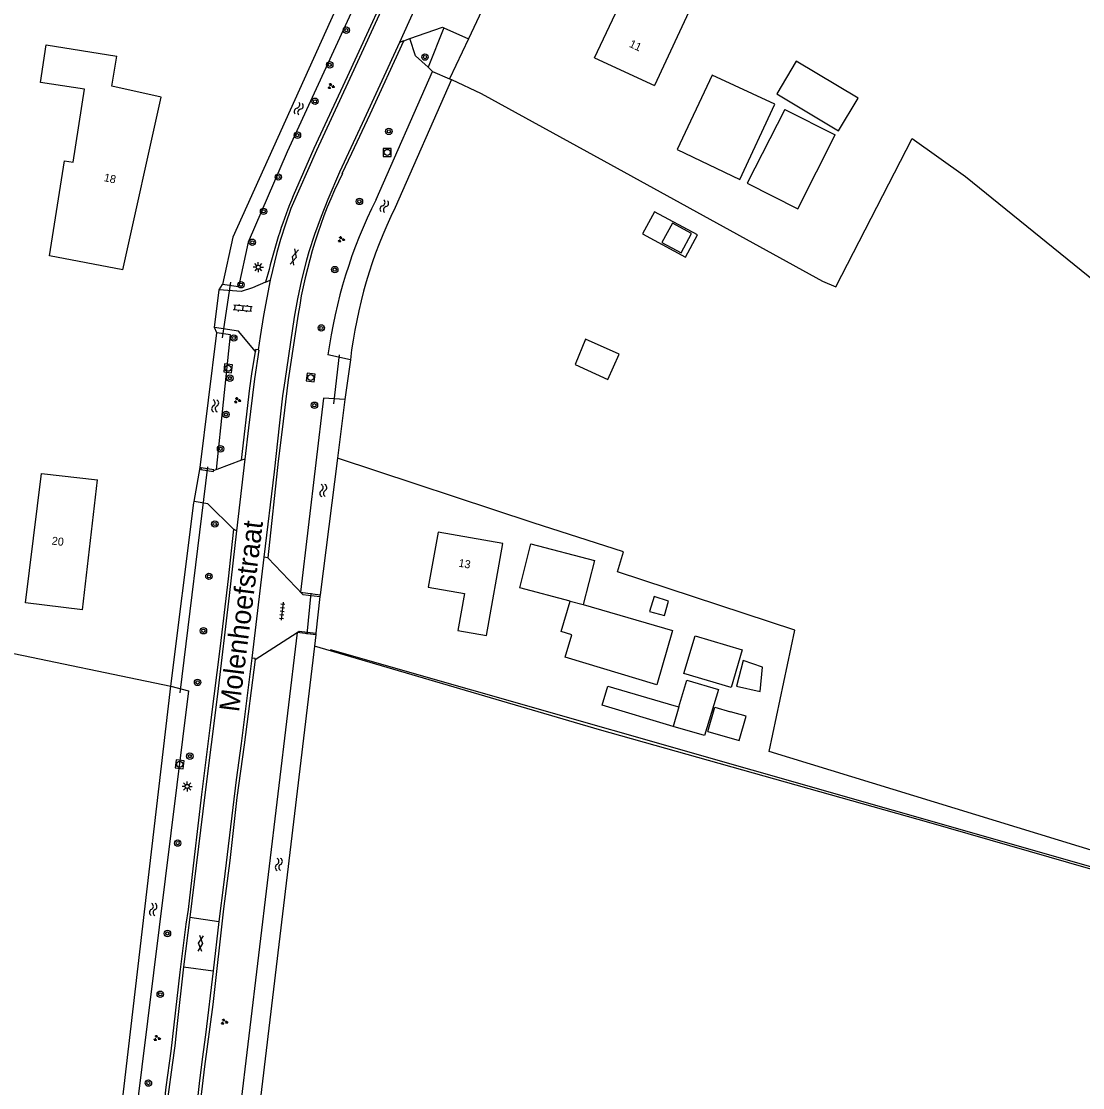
# Model space of a CAD drawing. Extents: x 136000 to 141000, y 400494 to 402006.
# Drawn here: x 137177.1 to 137309.6, y 401356.9 to 401490 of the extents above; entities that cross this region are included whole.
import ezdxf

# ---------------------------------------------------------------- set-up
doc = ezdxf.new("R2010")
doc.units = 0
for name, color, linetype in [('gg-afsc-draadraster', 7, 'Continuous'), ('gg-afsc-erfafscheiding', 7, 'Continuous'), ('gg-afsc-hekwerk', 7, 'Continuous'), ('gg-afsc-lijn draadraster', 7, 'Continuous'), ('gg-afsc-muur', 7, 'Continuous'), ('gg-anno-huisnummerreeks BGT', 7, 'Continuous'), ('gg-anno-openbare ruimte label', 7, 'Continuous'), ('gg-bbg-bijgebouw', 7, 'Continuous'), ('gg-bbg-gedigitaliseerde bebouwing', 7, 'Continuous'), ('gg-bbg-gedigitaliseerde bijgebouw', 7, 'Continuous'), ('gg-bbg-hoofdgebouw', 7, 'Continuous'), ('gg-bbg-overig bouwwerk', 7, 'Continuous'), ('gg-bbg-tussenscheiding', 7, 'Continuous'), ('gg-knt-bronhoudergrens', 7, 'Continuous'), ('gg-knt-verharding', 7, 'Continuous'), ('gg-kntw-bovenkant insteek waterloop', 7, 'Continuous'), ('gg-kntw-midden sloot', 7, 'Continuous'), ('gg-kwrk-duiker nz buis', 7, 'Continuous'), ('gt-grn-groengrens', 7, 'Continuous'), ('gt-symb-boom', 7, 'Continuous'), ('gt-symb-gesloten verharding', 7, 'Continuous'), ('gt-symb-groenvak', 7, 'Continuous'), ('gt-symb-klinker verharding', 7, 'Continuous'), ('gt-symb-lichtmast', 7, 'Continuous'), ('gt-symb-rioolschacht', 7, 'Continuous'), ('gt-symb-tegel verharding', 7, 'Continuous'), ('gt-symb-watersymbool', 7, 'Continuous')]:
    doc.layers.add(name, color=color, linetype=linetype)

# ---------------------------------------------------------------- blocks, each defined once
blk = doc.blocks.new('gt0-BOOM')
at = {"layer": 'gt-symb-boom'}
for radius in [0.4, 0.2]:
    blk.add_circle((0, 0), radius, dxfattribs=at)
blk = doc.blocks.new('gt0-WA')
at = {"layer": 'gt-symb-watersymbool'}
for centre, start, end in [((-0.32, 0.02), 28.0725, 151.9275), ((0.43, 0.42), 208.0725, 331.9275), ((-0.32, -0.43), 28.0725, 151.9275), ((0.43, -0.03), 208.0725, 331.9275)]:
    blk.add_arc(centre, 0.425, start, end, dxfattribs=at)
blk = doc.blocks.new('gt0-GRVAK')
at = {"layer": 'gt-symb-groenvak'}
for p, q in [((-0.11, 0.19), (-0.23, 0.24)), ((-0.18, 0.15), (0.09, 0.15)), ((-0.09, 0.21), (-0.16, 0.32)), ((-0.05, 0.21), (-0.05, 0.39)), ((0, 0.21), (0.06, 0.32)), ((0.02, 0.19), (0.13, 0.24)), ((0.26, -0.05), (0.2, 0.06)), ((0.3, -0.05), (0.3, 0.13)), ((0.35, -0.05), (0.41, 0.06)), ((-0.24, -0.23), (-0.36, -0.18)), ((-0.32, -0.26), (-0.05, -0.26)), ((-0.23, -0.21), (-0.29, -0.09)), ((-0.18, -0.2), (-0.18, -0.02)), ((-0.14, -0.21), (-0.07, -0.09)), ((-0.12, -0.23), (0, -0.18)), ((0.24, -0.07), (0.12, -0.02)), ((0.17, -0.11), (0.44, -0.11)), ((0.37, -0.07), (0.49, -0.02))]:
    blk.add_line(p, q, dxfattribs=at)
blk = doc.blocks.new('gt0-RS')
at = {"layer": 'gt-symb-rioolschacht'}
blk.add_lwpolyline([(-0.5, -0.5), (0.5, -0.5), (0.5, 0.5), (-0.5, 0.5)], close=True, dxfattribs=at)
blk.add_circle((0, 0), 0.375, dxfattribs=at)
blk = doc.blocks.new('gt0-LMAST')
at = {"layer": 'gt-symb-lichtmast'}
for p, q in [((-0.18, 0.17), (-0.45, 0.44)), ((-0.01, 0.25), (-0.01, 0.62)), ((0.17, 0.17), (0.44, 0.44)), ((-0.26, 0), (-0.63, 0)), ((-0.18, -0.18), (-0.45, -0.45)), ((-0.01, -0.25), (-0.01, -0.63)), ((0.44, -0.45), (0.17, -0.18)), ((0.24, 0), (0.62, 0))]:
    blk.add_line(p, q, dxfattribs=at)
blk.add_circle((-0.01, 0), 0.25, dxfattribs=at)
blk = doc.blocks.new('gt0-GESVH1')
at = {"layer": 'gt-symb-gesloten verharding'}
for p, q in [((-0.99, -0.26), (0.01, 0.24)), ((0.01, -0.26), (-0.99, 0.24)), ((0.01, 0.24), (1.01, -0.26)), ((1.01, 0.24), (0.01, -0.26))]:
    blk.add_line(p, q, dxfattribs=at)
blk = doc.blocks.new('gt0-KL1')
at = {"layer": 'gt-symb-klinker verharding'}
for p, q in [((-1.15, 0.3), (1.15, 0.3)), ((-1, -0.3), (-1, 0.3)), ((-0.5, 0.3), (-0.5, 0.45)), ((0, -0.3), (0, 0.3)), ((0.5, 0.3), (0.5, 0.45)), ((1, -0.3), (1, 0.3)), ((-1.15, -0.3), (1.15, -0.3)), ((-0.5, -0.45), (-0.5, -0.3)), ((0.5, -0.45), (0.5, -0.3))]:
    blk.add_line(p, q, dxfattribs=at)
blk = doc.blocks.new('gt0-TEG1')
at = {"layer": 'gt-symb-tegel verharding'}
for p, q in [((-1.12, 0), (1.12, 0)), ((-0.9, -0.25), (-0.9, 0.25)), ((-0.45, -0.25), (-0.45, 0.25)), ((0, -0.25), (0, 0.25)), ((0.45, -0.25), (0.45, 0.25)), ((0.9, -0.25), (0.9, 0.25))]:
    blk.add_line(p, q, dxfattribs=at)

msp = doc.modelspace()

# ---------------------------------------------------------------- linework, layer by layer
at = {"layer": 'gg-afsc-draadraster'}
for p, q in [((137135.1, 401419.6), (137195.75, 401407.02)), ((137270.41, 401398.85), (137273.64, 401413.99))]:
    msp.add_line(p, q, dxfattribs=at)
for points in [[(137230.77, 401482.78), (137234.48, 401481.03), (137249.8, 401472.6), (137277.09, 401457.58), (137278.74, 401456.88), (137288.3, 401475.4), (137294.96, 401470.65), (137321.19, 401449.38), (137348.39, 401427.9), (137349.24, 401427.23), (137328.94, 401404.71), (137314.3, 401385.4), (137270.41, 401398.85)], [(137273.64, 401413.99), (137251.48, 401421.3), (137252.23, 401423.76), (137240.98, 401427.4), (137216.53, 401435.46)], [(137315.51, 401382.74), (137290.37, 401389.96), (137249.24, 401401.56), (137213.65, 401412)]]:
    msp.add_lwpolyline(points, dxfattribs=at)
at = {"layer": 'gg-afsc-erfafscheiding'}
for p, q in [((137201.78, 401456.52), (137202.2, 401457.18)), ((137201.49, 401451.15), (137201.18, 401451.81)), ((137218.15, 401447.75), (137217.46, 401442.8)), ((137195.75, 401407.02), (137198.62, 401429.88)), ((137214.35, 401418.21), (137213.84, 401413.61)), ((137214.37, 401418.42), (137214.35, 401418.21)), ((137213.84, 401413.61), (137213.82, 401413.4))]:
    msp.add_line(p, q, dxfattribs=at)
at = {"layer": 'gg-afsc-hekwerk'}
for p, q in [((137234.87, 401492.08), (137232.88, 401487.85)), ((137232.88, 401487.85), (137230.54, 401482.87))]:
    msp.add_line(p, q, dxfattribs=at)
at = {"layer": 'gg-afsc-lijn draadraster'}
for p, q in [((137135.1, 401419.6), (137195.75, 401407.02)), ((137270.41, 401398.85), (137273.64, 401413.99))]:
    msp.add_line(p, q, dxfattribs=at)
for points in [[(137230.77, 401482.78), (137234.48, 401481.03), (137249.8, 401472.6), (137277.09, 401457.58), (137278.74, 401456.88), (137288.3, 401475.4), (137294.96, 401470.65), (137321.19, 401449.38), (137348.39, 401427.9), (137349.24, 401427.23), (137328.94, 401404.71), (137314.3, 401385.4), (137270.41, 401398.85)], [(137273.64, 401413.99), (137251.48, 401421.3), (137252.23, 401423.76), (137240.98, 401427.4), (137216.53, 401435.46)], [(137315.51, 401382.74), (137290.37, 401389.96), (137249.24, 401401.56), (137213.65, 401412)]]:
    msp.add_lwpolyline(points, dxfattribs=at)
at = {"layer": 'gg-afsc-muur'}
for points in [[(137199.52, 401434.28), (137199.48, 401434.08), (137201.06, 401433.81), (137201.07, 401433.89)], [(137201.07, 401433.89), (137201.09, 401434.01), (137199.52, 401434.28)]]:
    msp.add_lwpolyline(points, dxfattribs=at)
at = {"layer": 'gg-bbg-bijgebouw'}
msp.add_line((137272.37, 401479.03), (137278.68, 401475.85), dxfattribs=at)
for points in [[(137258.93, 401474.01), (137266.75, 401470.3), (137271.15, 401479.68), (137263.31, 401483.32), (137258.93, 401474.01)], [(137272.37, 401479.03), (137267.69, 401469.81), (137274, 401466.61), (137278.68, 401475.85)], [(137259.78, 401408.6), (137261.17, 401413.28), (137267.07, 401411.53), (137265.68, 401406.85), (137259.78, 401408.6)]]:
    msp.add_lwpolyline(points, dxfattribs=at)
at = {"layer": 'gg-bbg-gedigitaliseerde bebouwing'}
for points in [[(137189.75, 401459), (137180.59, 401460.75), (137182.44, 401472.61), (137183.54, 401472.44), (137184.96, 401481.55), (137179.44, 401482.41), (137180.18, 401487.12), (137189.01, 401485.68)], [(137184.69, 401416.55), (137177.6, 401417.39), (137179.59, 401433.58), (137186.58, 401432.75)]]:
    msp.add_lwpolyline(points, dxfattribs=at)
at = {"layer": 'gg-bbg-gedigitaliseerde bijgebouw'}
msp.add_lwpolyline([(137281.53, 401480.43), (137273.81, 401485.05), (137271.37, 401480.98), (137279.09, 401476.35), (137281.53, 401480.43)], dxfattribs=at)
at = {"layer": 'gg-bbg-hoofdgebouw'}
for p, q in [((137248.63, 401485.47), (137251.61, 401491.8)), ((137260.93, 401492.4), (137256.13, 401482.01)), ((137248.63, 401485.47), (137256.13, 401482.01)), ((137184.69, 401416.55), (137186.58, 401432.75)), ((137245.6, 401417.62), (137239.29, 401419.28))]:
    msp.add_line(p, q, dxfattribs=at)
for points in [[(137189.75, 401459), (137194.52, 401480.56), (137188.37, 401481.92), (137189.01, 401485.68)], [(137229.1, 401426.25), (137227.84, 401419.37), (137232.39, 401418.58)], [(137235.16, 401413.32), (137237.18, 401424.8), (137229.1, 401426.25)], [(137239.29, 401419.28), (137240.66, 401424.77), (137248.62, 401422.71), (137247.19, 401417.21)], [(137232.39, 401418.58), (137231.56, 401413.96), (137235.16, 401413.32)], [(137247.19, 401417.21), (137258.38, 401413.96), (137256.41, 401407.16), (137244.96, 401410.61), (137245.8, 401413.42), (137244.46, 401413.82), (137245.6, 401417.62)]]:
    msp.add_lwpolyline(points, dxfattribs=at)
at = {"layer": 'gg-bbg-overig bouwwerk'}
for p, q in [((137258.45, 401401.97), (137249.57, 401404.61)), ((137259.17, 401404.4), (137258.45, 401401.97))]:
    msp.add_line(p, q, dxfattribs=at)
for points in [[(137260.75, 401463.52), (137258.34, 401464.83), (137257.04, 401462.42), (137259.46, 401461.12), (137260.75, 401463.52)], [(137257.35, 401415.81), (137257.87, 401417.61), (137256.07, 401418.19), (137255.51, 401416.32), (137257.35, 401415.81)], [(137266.35, 401406.99), (137269.29, 401406.35), (137269.58, 401409.38), (137267.2, 401410.21), (137266.35, 401406.99)], [(137259.17, 401404.4), (137260.15, 401407.73), (137264.12, 401406.6), (137262.34, 401400.82), (137258.45, 401401.97)], [(137249.57, 401404.61), (137250.27, 401407.02), (137258.53, 401404.58), (137259.17, 401404.4)], [(137262.76, 401401.34), (137263.64, 401404.36), (137265.62, 401403.79)], [(137262.76, 401401.34), (137266.67, 401400.21), (137267.54, 401403.24), (137265.62, 401403.79)]]:
    msp.add_lwpolyline(points, dxfattribs=at)
at = {"layer": 'gg-bbg-tussenscheiding'}
msp.add_line((137245.6, 401417.62), (137247.19, 401417.21), dxfattribs=at)
at = {"layer": 'gg-knt-bronhoudergrens'}
msp.add_lwpolyline([(137246.19, 401447.17), (137250.3, 401445.32), (137251.71, 401448.45), (137247.52, 401450.34), (137246.19, 401447.17)], dxfattribs=at)
at = {"layer": 'gg-knt-verharding'}
for p, q in [((137229.48, 401498.84), (137224.27, 401487.41)), ((137229.8, 401489.24), (137232.88, 401487.85)), ((137224.84, 401487.62), (137224.27, 401487.41)), ((137224.84, 401487.62), (137225.55, 401487.87)), ((137208.01, 401459.04), (137207.57, 401457.45)), ((137207.57, 401457.45), (137205.92, 401456.75)), ((137207.57, 401457.45), (137208.13, 401457.7)), ((137201.18, 401451.81), (137201.78, 401456.52)), ((137204.19, 401451.34), (137201.18, 401451.81)), ((137206.29, 401448.81), (137204.19, 401451.34)), ((137204.95, 401435.34), (137203.95, 401426.42)), ((137204.95, 401435.34), (137204.56, 401435.21)), ((137198.66, 401430.08), (137199.39, 401434.3)), ((137199.52, 401434.28), (137199.39, 401434.3)), ((137201.44, 401434.05), (137201.07, 401433.89)), ((137198.62, 401429.88), (137198.66, 401430.08)), ((137203.95, 401426.42), (137203.56, 401426.61)), ((137207.33, 401423.1), (137205.85, 401410.51)), ((137207.85, 401423.04), (137207.33, 401423.1)), ((137206.24, 401410.32), (137211.51, 401413.72)), ((137211.51, 401413.72), (137211.75, 401413.87)), ((137211.75, 401413.87), (137213.84, 401413.61)), ((137198.12, 401378.13), (137197.33, 401371.96)), ((137198.12, 401378.13), (137201.74, 401377.62)), ((137201.74, 401377.62), (137201.03, 401371.43)), ((137197.33, 401371.96), (137201.03, 401371.43))]:
    msp.add_line(p, q, dxfattribs=at)
for points in [[(137227.21, 401502.78), (137224.64, 401497.23), (137217.82, 401482.35), (137213.91, 401473.91), (137210.72, 401466.67), (137210.03, 401464.71), (137209.42, 401462.79), (137208.97, 401461.15), (137208.13, 401457.7)], [(137226.93, 401503.03), (137224.53, 401497.9), (137217.74, 401483.09), (137213.59, 401474.14), (137211.02, 401468.25)], [(137225.55, 401487.87), (137229.63, 401489.32), (137229.8, 401489.24)], [(137224.27, 401487.41), (137219.63, 401477.27), (137216.8, 401471.21), (137215.35, 401467.79), (137214.51, 401465.68), (137213.67, 401463.42), (137212.94, 401461.23), (137212.65, 401460.22), (137212.05, 401457.74), (137211.56, 401455.37), (137211.14, 401453.07), (137209.95, 401445.13), (137209.68, 401443.27), (137209.28, 401439.87), (137208.62, 401433.77), (137207.33, 401423.1)], [(137217.14, 401471.04), (137218.32, 401473.59), (137220.6, 401478.43), (137224.84, 401487.62)], [(137254.63, 401463.48), (137259.98, 401460.59), (137261.48, 401463.38), (137256.13, 401466.26), (137254.63, 401463.48)], [(137205.92, 401456.75), (137204.51, 401456.29), (137201.78, 401456.52)], [(137208.13, 401457.7), (137207.29, 401453.3), (137206.87, 401450.68), (137206.63, 401449)], [(137211.62, 401453.46), (137210.36, 401445.24), (137209.59, 401438.72), (137209.12, 401435.1), (137207.85, 401423.04)], [(137204.56, 401435.21), (137205.61, 401444.22), (137205.86, 401446.02), (137206.29, 401448.81)], [(137206.63, 401449), (137206.7, 401448.98), (137206.16, 401445.4), (137205.41, 401439.27), (137204.95, 401435.34)], [(137206.63, 401449), (137206.32, 401449.03), (137206.29, 401448.81)], [(137204.56, 401435.21), (137201.48, 401434.06), (137201.44, 401434.05)], [(137203.56, 401426.61), (137200.37, 401429.79), (137198.66, 401430.08)], [(137203.56, 401426.61), (137202.89, 401420.42), (137201.89, 401412), (137200.67, 401402.48), (137199.58, 401393.47), (137198.66, 401385.66), (137197.88, 401379.11), (137197.6, 401377.27), (137196.84, 401371.3), (137195.73, 401361.4), (137195.12, 401356.9), (137194.51, 401351.5), (137192.93, 401338.38), (137191.77, 401329.36), (137191.21, 401324.6), (137191.11, 401324.61), (137190.93, 401323.55)], [(137203.95, 401426.42), (137203.01, 401418.32), (137201.54, 401406.01), (137199.97, 401393.44), (137198.12, 401378.13)], [(137207.85, 401423.04), (137212.21, 401418.43), (137214.35, 401418.21)], [(137206.24, 401410.32), (137204.87, 401399.67), (137203.99, 401393.09), (137203.11, 401385.24), (137202.32, 401379.19), (137200.96, 401367.26), (137199.93, 401359.52), (137199.42, 401355.28), (137198.67, 401347.87), (137198.29, 401347.85)], [(137205.85, 401410.51), (137204.51, 401399.84), (137203.88, 401395.31), (137202.36, 401382.54), (137201.74, 401377.62)], [(137206.24, 401410.32), (137206.24, 401410.44), (137205.85, 401410.51)], [(137197.33, 401371.96), (137196.49, 401364.51), (137196.24, 401362.1), (137195.88, 401359.7), (137195.35, 401355.72), (137194.92, 401351.52), (137193.46, 401339.54), (137191.67, 401325.24), (137191.54, 401324.07), (137191.43, 401323.99), (137191.38, 401323.73)], [(137201.03, 401371.43), (137200.08, 401363.46), (137199.63, 401360.43), (137199.26, 401357.36), (137198.23, 401348), (137198.27, 401347.98), (137198.29, 401347.85)]]:
    msp.add_lwpolyline(points, dxfattribs=at)
for centre, radius, start, end in [((137271.21, 401444.42), 60.26, 153.7858, 171.3703), ((137268.77, 401444.26), 62.54, 157.4483, 166.3362)]:
    msp.add_arc(centre, radius, start, end, dxfattribs=at)
at = {"layer": 'gg-kntw-bovenkant insteek waterloop'}
for p, q in [((137221.35, 401467.78), (137228.38, 401483.76)), ((137228.38, 401483.76), (137230.54, 401482.87)), ((137230.77, 401482.78), (137223.75, 401466.8)), ((137230.54, 401482.87), (137230.77, 401482.78)), ((137199.39, 401434.3), (137201.49, 401451.15)), ((137218.15, 401447.75), (137215.34, 401448.38)), ((137217.46, 401442.8), (137216.53, 401435.46)), ((137216.53, 401435.46), (137214.37, 401418.42)), ((137213.82, 401413.4), (137211.51, 401413.72)), ((137213.82, 401413.4), (137213.65, 401412)), ((137213.65, 401412), (137206.6, 401352.93)), ((137189.49, 401353.62), (137195.75, 401407.02))]:
    msp.add_line(p, q, dxfattribs=at)
for points in [[(137222.32, 401500), (137210.24, 401473.74), (137205.37, 401462.46), (137204.17, 401456.87), (137202.2, 401457.18)], [(137220.13, 401500), (137203.46, 401463.08), (137202.2, 401457.18)], [(137201.44, 401434.05), (137203.19, 401450.9), (137201.49, 401451.15)], [(137217.46, 401442.8), (137214.8, 401442.97), (137211.92, 401418.74), (137214.37, 401418.42)], [(137211.51, 401413.72), (137204.26, 401353.26), (137206.6, 401352.93)], [(137195.75, 401407.02), (137197.93, 401406.4), (137191.36, 401353.41), (137189.49, 401353.62)]]:
    msp.add_lwpolyline(points, dxfattribs=at)
for centre, radius, start, end in [((137276.84, 401439.97), 62.07, 153.3837, 172.2175), ((137276.02, 401441.1), 58.25, 153.8188, 173.4471)]:
    msp.add_arc(centre, radius, start, end, dxfattribs=at)
at = {"layer": 'gg-kntw-midden sloot'}
for p, q in [((137215.63, 401411.6), (137285.92, 401391.52)), ((137285.92, 401391.52), (137314.16, 401383.46))]:
    msp.add_line(p, q, dxfattribs=at)
at = {"layer": 'gg-kwrk-duiker nz buis'}
for p, q in [((137203.18, 401457.46), (137202.15, 401450.52)), ((137216.73, 401448.37), (137216.06, 401442.26)), ((137196.88, 401406.18), (137200.36, 401434.39)), ((137213.21, 401418.6), (137212.72, 401413.5))]:
    msp.add_line(p, q, dxfattribs=at)
at = {"layer": 'gt-grn-groengrens'}
for p, q in [((137229.8, 401489.24), (137227.84, 401484.3)), ((137227.84, 401484.3), (137228.38, 401483.76))]:
    msp.add_line(p, q, dxfattribs=at)
msp.add_lwpolyline([(137227.84, 401484.3), (137226.28, 401485.71), (137225.55, 401487.87)], dxfattribs=at)

# ---------------------------------------------------------------- block references
at = {"layer": 'gt-symb-boom'}
for p in [(137217.64, 401488.93), (137227.46, 401485.57), (137215.57, 401484.6), (137213.73, 401480.05), (137222.95, 401476.29), (137211.54, 401475.82), (137209.15, 401470.59), (137219.28, 401467.54), (137207.31, 401466.3), (137205.9, 401462.44), (137216.2, 401459.03), (137204.49, 401457.13), (137214.52, 401451.74), (137203.59, 401450.49), (137203.1, 401445.47), (137213.66, 401442.09), (137202.62, 401440.93), (137201.94, 401436.64), (137201.22, 401427.25), (137200.49, 401420.72), (137199.8, 401413.92), (137199.07, 401407.47), (137198.1, 401398.26), (137196.59, 401387.4), (137195.31, 401376.11), (137194.41, 401368.52), (137192.93, 401357.43)]:
    msp.add_blockref('gt0-BOOM', p, dxfattribs=at)
at = {"layer": 'gt-symb-gesloten verharding'}
for p, rotation in [((137211.13, 401460.6), 73.97589034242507), ((137199.44, 401374.86), 83.62817759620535)]:
    msp.add_blockref('gt0-GESVH1', p, dxfattribs=dict(at, rotation=rotation))
at = {"layer": 'gt-symb-groenvak'}
for p in [(137215.72, 401481.93), (137216.99, 401462.8), (137204.03, 401442.7), (137202.39, 401365.08), (137193.99, 401363.04)]:
    msp.add_blockref('gt0-GRVAK', p, dxfattribs=at)
at = {"layer": 'gt-symb-klinker verharding', "rotation": 174.1469086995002}
msp.add_blockref('gt0-KL1', (137204.7, 401454.19), dxfattribs=at)
at = {"layer": 'gt-symb-lichtmast'}
for p in [(137206.66, 401459.33), (137197.78, 401394.48)]:
    msp.add_blockref('gt0-LMAST', p, dxfattribs=at)
at = {"layer": 'gt-symb-rioolschacht'}
msp.add_blockref('gt0-RS', (137222.75, 401473.67), dxfattribs=at)
for p, rotation in [((137202.88, 401446.7), -6.030008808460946), ((137213.19, 401445.55), -7.004259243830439), ((137196.84, 401397.25), -7.004259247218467)]:
    msp.add_blockref('gt0-RS', p, dxfattribs=dict(at, rotation=rotation))
at = {"layer": 'gt-symb-tegel verharding', "rotation": -95.45391888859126}
msp.add_blockref('gt0-TEG1', (137209.63, 401416.37), dxfattribs=at)
at = {"layer": 'gt-symb-watersymbool'}
for p, rotation in [((137211.72, 401479.18), -108.00007459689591), ((137222.39, 401467), -104.00844348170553), ((137201.27, 401442.06), -89.02606556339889), ((137214.77, 401431.49), -87.99346106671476), ((137209.22, 401384.8), -90.00000000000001), ((137193.54, 401379.17), -93.03686894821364)]:
    msp.add_blockref('gt0-WA', p, dxfattribs=dict(at, rotation=rotation))

# ---------------------------------------------------------------- texts
at = {"layer": 'gg-anno-huisnummerreeks BGT'}
for s, rotation, p in [('11', 334.8, (137252.86, 401486.89)), ('18', 347.5, (137187.31, 401470.09)), ('20', 353.3, (137180.83, 401424.69)), ('13', 349.6, (137231.59, 401421.94))]:
    msp.add_text(s, height=1, rotation=rotation, dxfattribs=at).set_placement(p)
at = {"layer": 'gg-anno-openbare ruimte label'}
msp.add_text('Molenhoefstraat', height=2.5, rotation=82.8, dxfattribs=at).set_placement((137204.24, 401403.7))

doc.saveas('drawing.dxf')
